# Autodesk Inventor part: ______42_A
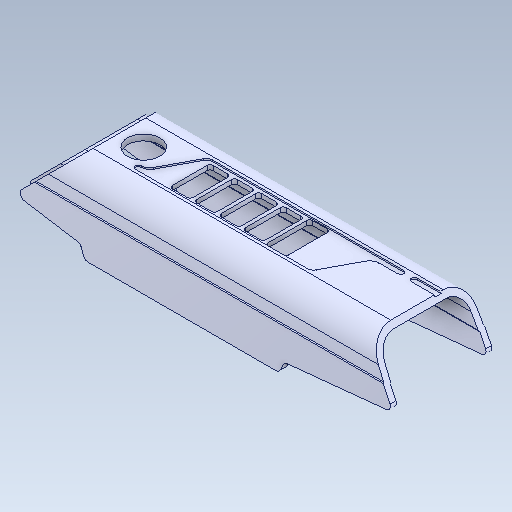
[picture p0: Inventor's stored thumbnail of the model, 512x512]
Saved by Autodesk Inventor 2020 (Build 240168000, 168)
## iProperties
Created: 2017-09
Part Number: ______42_A
Material: Générique
Document SubType Name: Modeling
Designer: bruno
Density: 1 g/cm^3
Appearance: Par défaut
Author: bruno
Sending System: SolidWorks 2016
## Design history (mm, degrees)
feature "Importée1"
node "Solide1"
